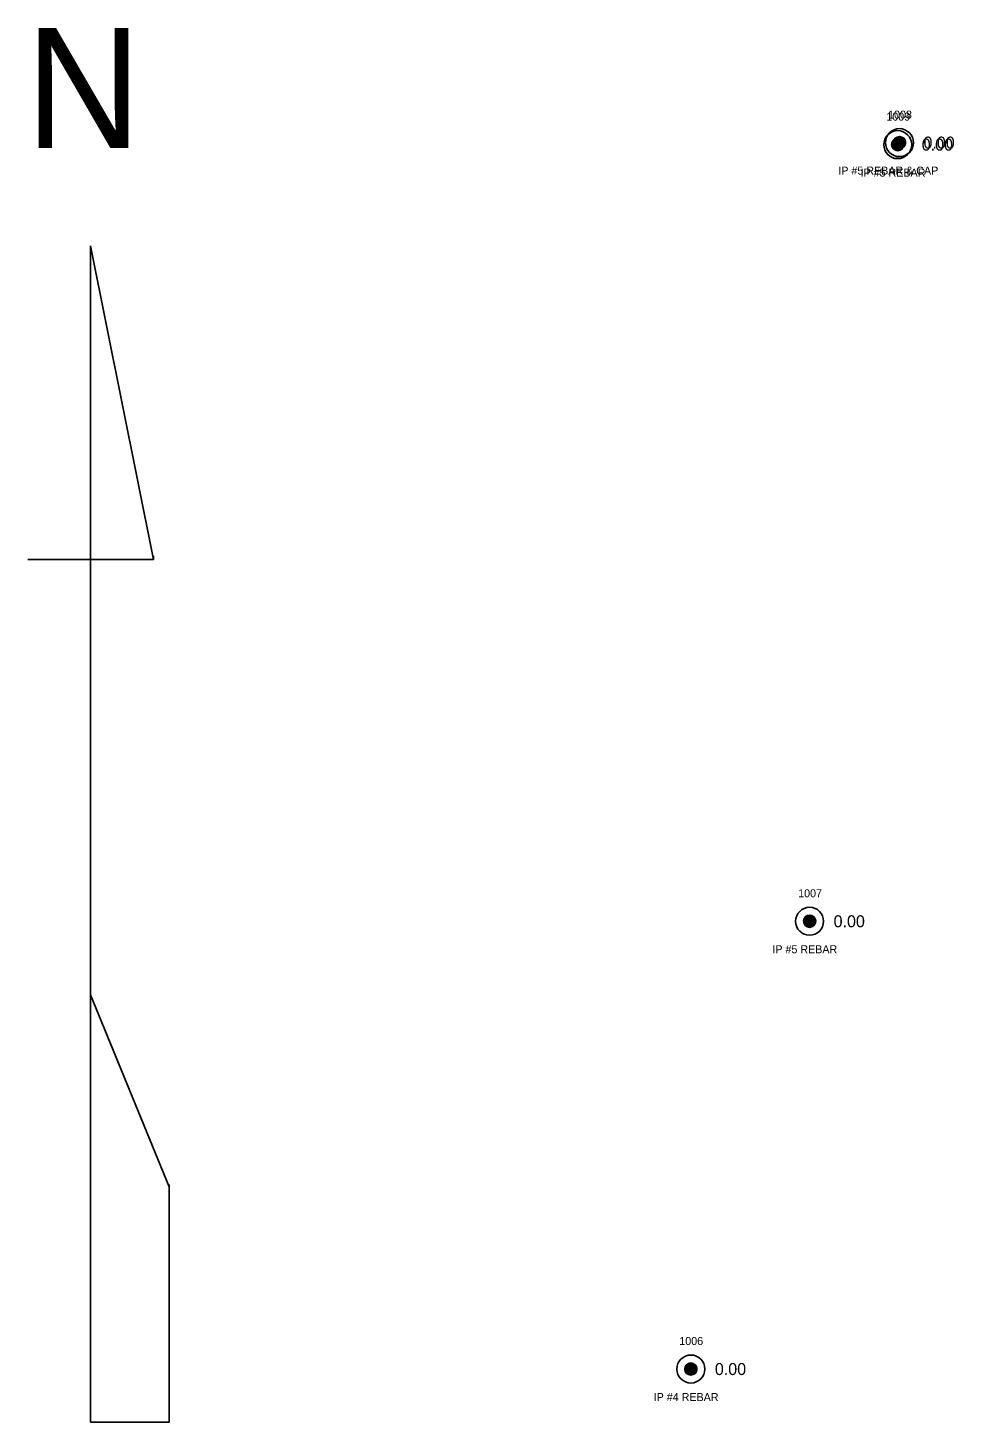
# Model space of a CAD drawing. Extents: x 1740701 to 1743138, y 748181 to 751839.
# Drawn here: x 1740705.8 to 1740821.6, y 749442.4 to 749616.6 of the extents above; entities that cross this region are included whole.
import ezdxf

# ---------------------------------------------------------------- set-up
doc = ezdxf.new("R2010")
doc.units = 0
for name, color, linetype in [('RD_EX_DV_Prop_txCode', 7, 'Continuous'), ('RD_EX_DV_PropPin', 7, 'Continuous'), ('RD_EX_Misc', 7, 'Continuous'), ('RD_EX_TX_DV_Prop_ELEV', 7, 'Continuous'), ('RD_SMD_Locator', 7, 'Continuous')]:
    doc.layers.add(name, color=color, linetype=linetype)

msp = doc.modelspace()

# ---------------------------------------------------------------- linework, layer by layer
at = {"layer": 'RD_EX_DV_PropPin'}
for p, q in [((1740813.79, 749601.86), (1740813.79, 749602.25)), ((1740813.82, 749601.76), (1740813.82, 749602.35)), ((1740813.86, 749601.68), (1740813.86, 749602.42)), ((1740813.89, 749601.63), (1740813.89, 749602.48)), ((1740813.93, 749601.58), (1740813.93, 749602.53)), ((1740813.96, 749601.54), (1740813.96, 749602.57)), ((1740814, 749601.5), (1740814, 749602.6)), ((1740814.01, 749602.1), (1740814.01, 749602.49)), ((1740814.03, 749601.47), (1740814.03, 749602.64)), ((1740814.04, 749602), (1740814.04, 749602.6)), ((1740814.07, 749601.44), (1740814.07, 749602.66)), ((1740814.08, 749601.93), (1740814.08, 749602.67)), ((1740814.1, 749601.42), (1740814.1, 749602.69)), ((1740814.11, 749601.87), (1740814.11, 749602.72)), ((1740814.14, 749601.4), (1740814.14, 749602.71)), ((1740814.15, 749601.82), (1740814.15, 749602.77)), ((1740814.17, 749601.38), (1740814.17, 749602.73)), ((1740814.18, 749601.78), (1740814.18, 749602.81)), ((1740814.21, 749601.36), (1740814.21, 749602.75)), ((1740814.22, 749601.75), (1740814.22, 749602.85)), ((1740814.24, 749601.35), (1740814.24, 749602.76)), ((1740814.25, 749601.72), (1740814.25, 749602.88)), ((1740814.28, 749601.33), (1740814.28, 749602.77)), ((1740814.29, 749601.69), (1740814.29, 749602.91)), ((1740814.31, 749601.32), (1740814.31, 749602.79)), ((1740814.32, 749601.66), (1740814.32, 749602.93)), ((1740814.35, 749601.31), (1740814.35, 749602.79)), ((1740814.36, 749601.64), (1740814.36, 749602.95)), ((1740814.38, 749601.31), (1740814.38, 749602.8)), ((1740814.39, 749601.62), (1740814.39, 749602.97)), ((1740814.42, 749601.3), (1740814.42, 749602.81)), ((1740814.43, 749601.6), (1740814.43, 749602.99)), ((1740814.45, 749601.3), (1740814.45, 749602.81)), ((1740814.46, 749601.59), (1740814.46, 749603)), ((1740814.49, 749601.29), (1740814.49, 749602.81)), ((1740814.5, 749601.58), (1740814.5, 749603.02)), ((1740814.52, 749601.29), (1740814.52, 749602.81)), ((1740814.53, 749601.57), (1740814.53, 749603.03)), ((1740814.56, 749601.29), (1740814.56, 749602.81)), ((1740814.57, 749601.56), (1740814.57, 749603.04)), ((1740814.59, 749601.3), (1740814.59, 749602.81)), ((1740814.6, 749601.55), (1740814.6, 749603.05)), ((1740814.63, 749601.3), (1740814.63, 749602.81)), ((1740814.64, 749601.54), (1740814.64, 749603.05)), ((1740814.66, 749601.31), (1740814.66, 749602.8)), ((1740814.67, 749601.54), (1740814.67, 749603.05)), ((1740814.7, 749601.31), (1740814.7, 749602.79)), ((1740814.71, 749601.54), (1740814.71, 749603.06)), ((1740814.73, 749601.32), (1740814.73, 749602.79)), ((1740814.74, 749601.54), (1740814.74, 749603.06)), ((1740814.77, 749601.33), (1740814.77, 749602.77)), ((1740814.78, 749601.54), (1740814.78, 749603.06)), ((1740814.8, 749601.35), (1740814.8, 749602.76)), ((1740814.81, 749601.54), (1740814.81, 749603.05)), ((1740814.84, 749601.36), (1740814.84, 749602.75)), ((1740814.85, 749601.54), (1740814.85, 749603.05)), ((1740814.87, 749601.38), (1740814.87, 749602.73)), ((1740814.88, 749601.55), (1740814.88, 749603.05)), ((1740814.91, 749601.4), (1740814.91, 749602.71)), ((1740814.92, 749601.56), (1740814.92, 749603.04)), ((1740814.94, 749601.42), (1740814.94, 749602.69)), ((1740814.95, 749601.57), (1740814.95, 749603.03)), ((1740814.98, 749601.44), (1740814.98, 749602.66)), ((1740814.99, 749601.58), (1740814.99, 749603.02)), ((1740815.01, 749601.47), (1740815.01, 749602.64)), ((1740815.02, 749601.59), (1740815.02, 749603)), ((1740815.05, 749601.5), (1740815.05, 749602.6)), ((1740815.06, 749601.6), (1740815.06, 749602.99)), ((1740815.08, 749601.54), (1740815.08, 749602.57)), ((1740815.09, 749601.62), (1740815.09, 749602.97)), ((1740815.12, 749601.58), (1740815.12, 749602.53)), ((1740815.13, 749601.64), (1740815.13, 749602.95)), ((1740815.15, 749601.63), (1740815.15, 749602.48)), ((1740815.16, 749601.66), (1740815.16, 749602.93)), ((1740815.19, 749601.68), (1740815.19, 749602.42)), ((1740815.2, 749601.69), (1740815.2, 749602.91)), ((1740815.22, 749601.76), (1740815.22, 749602.35)), ((1740815.23, 749601.72), (1740815.23, 749602.88)), ((1740815.26, 749601.86), (1740815.26, 749602.25)), ((1740815.27, 749601.75), (1740815.27, 749602.85)), ((1740815.3, 749601.78), (1740815.3, 749602.81)), ((1740815.34, 749601.82), (1740815.34, 749602.77)), ((1740815.37, 749601.87), (1740815.37, 749602.72)), ((1740815.41, 749601.93), (1740815.41, 749602.67)), ((1740815.44, 749602), (1740815.44, 749602.6)), ((1740815.48, 749602.1), (1740815.48, 749602.49)), ((1740802.77, 749504.81), (1740802.77, 749505.2)), ((1740802.81, 749504.71), (1740802.81, 749505.3)), ((1740802.84, 749504.63), (1740802.84, 749505.37)), ((1740802.88, 749504.58), (1740802.88, 749505.43)), ((1740802.91, 749504.53), (1740802.91, 749505.48)), ((1740802.95, 749504.49), (1740802.95, 749505.52)), ((1740802.98, 749504.45), (1740802.98, 749505.56)), ((1740803.02, 749504.42), (1740803.02, 749505.59)), ((1740803.05, 749504.39), (1740803.05, 749505.61)), ((1740803.09, 749504.37), (1740803.09, 749505.64)), ((1740803.12, 749504.35), (1740803.12, 749505.66)), ((1740803.16, 749504.33), (1740803.16, 749505.68)), ((1740803.19, 749504.31), (1740803.19, 749505.7)), ((1740803.23, 749504.3), (1740803.23, 749505.71)), ((1740803.26, 749504.28), (1740803.26, 749505.72)), ((1740803.3, 749504.27), (1740803.3, 749505.74)), ((1740803.33, 749504.26), (1740803.33, 749505.75)), ((1740803.37, 749504.26), (1740803.37, 749505.75)), ((1740803.4, 749504.25), (1740803.4, 749505.76)), ((1740803.44, 749504.25), (1740803.44, 749505.76)), ((1740803.47, 749504.24), (1740803.47, 749505.76)), ((1740803.51, 749504.24), (1740803.51, 749505.77)), ((1740803.54, 749504.24), (1740803.54, 749505.76)), ((1740803.58, 749504.25), (1740803.58, 749505.76)), ((1740803.62, 749504.25), (1740803.62, 749505.76)), ((1740803.65, 749504.26), (1740803.65, 749505.75)), ((1740803.69, 749504.26), (1740803.69, 749505.75)), ((1740803.72, 749504.27), (1740803.72, 749505.74)), ((1740803.76, 749504.28), (1740803.76, 749505.72)), ((1740803.79, 749504.3), (1740803.79, 749505.71)), ((1740803.83, 749504.31), (1740803.83, 749505.7)), ((1740803.86, 749504.33), (1740803.86, 749505.68)), ((1740803.9, 749504.35), (1740803.9, 749505.66)), ((1740803.93, 749504.37), (1740803.93, 749505.64)), ((1740803.97, 749504.39), (1740803.97, 749505.61)), ((1740804, 749504.42), (1740804, 749505.59)), ((1740804.04, 749504.45), (1740804.04, 749505.56)), ((1740804.07, 749504.49), (1740804.07, 749505.52)), ((1740804.11, 749504.53), (1740804.11, 749505.48)), ((1740804.14, 749504.58), (1740804.14, 749505.43)), ((1740804.18, 749504.63), (1740804.18, 749505.37)), ((1740804.21, 749504.71), (1740804.21, 749505.3)), ((1740804.25, 749504.81), (1740804.25, 749505.2)), ((1740787.94, 749448.85), (1740787.94, 749449.24)), ((1740787.97, 749448.75), (1740787.97, 749449.35)), ((1740788.01, 749448.68), (1740788.01, 749449.42)), ((1740788.04, 749448.62), (1740788.04, 749449.47)), ((1740788.08, 749448.57), (1740788.08, 749449.52)), ((1740788.11, 749448.53), (1740788.11, 749449.56)), ((1740788.15, 749448.5), (1740788.15, 749449.6)), ((1740788.18, 749448.47), (1740788.18, 749449.63)), ((1740788.22, 749448.44), (1740788.22, 749449.66)), ((1740788.25, 749448.41), (1740788.25, 749449.68)), ((1740788.29, 749448.39), (1740788.29, 749449.7)), ((1740788.32, 749448.37), (1740788.32, 749449.72)), ((1740788.36, 749448.36), (1740788.36, 749449.74)), ((1740788.39, 749448.34), (1740788.39, 749449.76)), ((1740788.43, 749448.33), (1740788.43, 749449.77)), ((1740788.46, 749448.32), (1740788.46, 749449.78)), ((1740788.5, 749448.31), (1740788.5, 749449.79)), ((1740788.53, 749448.3), (1740788.53, 749449.8)), ((1740788.57, 749448.29), (1740788.57, 749449.8)), ((1740788.6, 749448.29), (1740788.6, 749449.81)), ((1740788.64, 749448.29), (1740788.64, 749449.81)), ((1740788.67, 749448.29), (1740788.67, 749449.81)), ((1740788.71, 749448.29), (1740788.71, 749449.81)), ((1740788.74, 749448.29), (1740788.74, 749449.81)), ((1740788.78, 749448.29), (1740788.78, 749449.8)), ((1740788.81, 749448.3), (1740788.81, 749449.8)), ((1740788.85, 749448.31), (1740788.85, 749449.79)), ((1740788.88, 749448.32), (1740788.88, 749449.78)), ((1740788.92, 749448.33), (1740788.92, 749449.77)), ((1740788.95, 749448.34), (1740788.95, 749449.76)), ((1740788.99, 749448.36), (1740788.99, 749449.74)), ((1740789.02, 749448.37), (1740789.02, 749449.72)), ((1740789.06, 749448.39), (1740789.06, 749449.7)), ((1740789.09, 749448.41), (1740789.09, 749449.68)), ((1740789.13, 749448.44), (1740789.13, 749449.66)), ((1740789.16, 749448.47), (1740789.16, 749449.63)), ((1740789.2, 749448.5), (1740789.2, 749449.6)), ((1740789.23, 749448.53), (1740789.23, 749449.56)), ((1740789.27, 749448.57), (1740789.27, 749449.52)), ((1740789.3, 749448.62), (1740789.3, 749449.47)), ((1740789.34, 749448.68), (1740789.34, 749449.42)), ((1740789.37, 749448.75), (1740789.37, 749449.35)), ((1740789.41, 749448.85), (1740789.41, 749449.24))]:
    msp.add_line(p, q, dxfattribs=at)
for centre, radius in [((1740814.52, 749602.05), 1.75), ((1740814.74, 749602.3), 1.75), ((1740814.52, 749602.05), 0.761), ((1740814.74, 749602.3), 0.761), ((1740803.51, 749505), 1.75), ((1740803.51, 749505), 0.761), ((1740788.67, 749449.05), 1.75), ((1740788.67, 749449.05), 0.761)]:
    msp.add_circle(centre, radius, dxfattribs=at)
at = {"layer": 'RD_EX_Misc'}
for p, q in [((1740721.51, 749550.22), (1740713.67, 749589.42)), ((1740713.67, 749589.42), (1740713.67, 749589.42)), ((1740713.67, 749589.42), (1740713.67, 749550.22)), ((1740705.83, 749550.22), (1740713.67, 749550.22)), ((1740713.67, 749495.82), (1740713.67, 749550.22)), ((1740713.67, 749550.22), (1740721.51, 749550.22)), ((1740721.51, 749550.22), (1740721.51, 749550.68)), ((1740723.47, 749471.82), (1740713.67, 749495.82)), ((1740713.67, 749495.82), (1740713.67, 749442.42)), ((1740723.47, 749442.42), (1740723.47, 749472.09)), ((1740723.47, 749472.09), (1740723.47, 749471.82)), ((1740713.67, 749442.42), (1740723.47, 749442.42))]:
    msp.add_line(p, q, dxfattribs=at)
at = {"layer": 'RD_SMD_Locator'}
for centre in [(1740814.52, 749602.05), (1740814.74, 749602.3), (1740803.51, 749505), (1740788.67, 749449.05)]:
    msp.add_circle(centre, 0.15, dxfattribs=at)

# ---------------------------------------------------------------- texts
at = {"layer": 'RD_EX_DV_Prop_txCode'}
for s, p in [('1009', (1740813.1, 749605.05)), ('1008', (1740813.32, 749605.3)), ('IP #5 REBAR & CAP', (1740807.1, 749598.3)), ('IP #5 REBAR', (1740809.88, 749598.05)), ('1007', (1740802.08, 749508)), ('IP #5 REBAR', (1740798.86, 749501)), ('1006', (1740787.23, 749452.05)), ('IP #4 REBAR', (1740784.03, 749445.05))]:
    msp.add_text(s, height=1, dxfattribs=at).set_placement(p)
at = {"layer": 'RD_EX_Misc'}
msp.add_text('N', height=15, dxfattribs=at).set_placement((1740705.52, 749601.64))
at = {"layer": 'RD_EX_TX_DV_Prop_ELEV'}
for p in [(1740817.52, 749601.3), (1740817.74, 749601.55), (1740806.51, 749504.25), (1740791.67, 749448.3)]:
    msp.add_text('0.00', height=1.5, dxfattribs=at).set_placement(p)

doc.saveas('drawing.dxf')
